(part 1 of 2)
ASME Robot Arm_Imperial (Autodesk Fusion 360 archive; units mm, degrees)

design "ASME Robot Arm - Imperial" references "Hexagon Socket Head Cap Screw ANSI B18.3 - 1/4-28 UNF x 3/8 Steel Grade 2 Plain"
parameter "d400" = 0
sketch "Sketch1" plane through (0, 0, 0) normal (0, 1, 0) x axis (1, 0, 0)
  line L1 (125, 0) -> (0, 0)
  line L2 (0, -40) -> (0, 0)
  line L3 (125, -15) -> (125, 0)
  line L4 (115, -15) -> (125, -15)
  line L5 (60, -45) -> (60, -40)
  curve K1 (115, -15) -> (60, -40)
  line L6 (55, -40) -> (60, -40)
  line L7 (55, -33) -> (55, -40)
  line L8 (54, -33) -> (55, -33)
  line L9 (54, -28) -> (54, -33)
  line L10 (55, -28) -> (54, -28)
  line L11 (55, -15.5519) -> (55, -28)
  line L12 (64, -8) -> (55, -15.5519)
  line L13 (64, 0) -> (64, -8)
  point P1 (0, 0)
  point P2 (0, 0)
  point P4 (0, 0)
  point P5 (0, -40)
  point P8 (60, -40)
  point P17 (64, 0)
  point P3 (125, 0)
  point P6 (125, -15)
  point P7 (115, -15)
  point P9 (60, -45)
  point P10 (55, -40)
  point P11 (55, -33)
  point P12 (54, -33)
  point P13 (54, -28)
  point P16 (64, -8)
  coincident P1 P2
  horizontal L1
  coincident P1 P4
  perpendicular L1 L2
  perpendicular L1 L3
  perpendicular L3 L4
  horizontal P5 P8
  perpendicular L5 L6
  perpendicular L6 L7
  perpendicular L7 L8
  perpendicular L8 L9
  perpendicular L9 L10
  perpendicular L4 L11
  coincident L1 P17
  perpendicular L1 L13
  collinear L7 L11
  dimension "d2" distance P4 P5 = 40
  dimension "d3" = 250
  dimension "d4" distance P3 P6 = 15
  dimension "d5" distance P6 P7 = 10
  dimension "d9" distance P8 P9 = 5
  dimension "d16" = 120
  dimension "d17" distance P8 P10 = 5
  dimension "d18" distance P10 P11 = 7
  dimension "d19" distance P12 P13 = 5
  dimension "d20" distance P16 P17 = 8
  dimension "d21" = 128
  dimension "d22" angle L12 L13 = 50
  dimension "d23" = 108
revolve "Revolve1" sketch "Sketch1" AlongAngle 360
sketch "Sketch2" plane through (0, 0, 40) normal (0, 0, 1) x axis (-1, 0, 0)
  line L1 (0, 100) -> (0, 0)
  circle C1 centre (0, 0) radius 30
  circle C2 centre (0, 0) radius 25
  circle C3 centre (0, 0) radius 60
  circle C4 centre (0, 0) radius 55
  point P2 (0, 0)
  point P3 (0, 100)
  vertical L1
  dimension "d8" distance P2 P3 = 100
hole "Hole1" HoleDiameter 9 TipAngle 118 CBDepth 33 CBDiameter 15
circular_pattern "C-Pattern1" TotalAngle 360
sketch "Sketch1" plane through (0, 0, 0) normal (1, 0, 0) x axis (0, 1, 0)
sketch "Sketch2" plane through (0, 0, 0) normal (1, 0, 0) x axis (0, 1, 0)
  line L1 (0, 225) -> (0, 0)
  line L2 (-55, 40) -> (55, 40)
  line L3 (-55, 181.6987) -> (-55, 40)
  curve K1 (-55, 145) -> (-70, 225)
  curve K2 (-53.2004, 137.205) -> (-56.7996, 152.795)
  curve K3 (-70, 217) -> (-70, 233)
  curve K4 (55, 145) -> (70, 225)
  curve K5 (70, 217) -> (70, 233)
  curve K6 (53.2004, 137.205) -> (56.7996, 152.795)
  line L4 (55, 145) -> (-55, 145)
  circle C1 centre (0, 225) radius 70
  point P1 (0, 0)
  point P2 (0, 0)
  point P3 (0, 225)
  point P6 (0, 225)
  point P5 (-55, 40)
  point P7 (-55, 40)
  point P8 (-55, 181.6987)
  point P9 (-70, 225)
  point P10 (-55, 145)
  point P15 (70, 225)
  point P16 (55, 145)
  point P11 (-56.7996, 152.795)
  point P19 (56.7996, 152.795)
  point P12 (-53.2004, 137.205)
  point P20 (53.2004, 137.205)
  point P13 (-70, 233)
  point P17 (70, 233)
  point P14 (-70, 217)
  point P18 (70, 217)
  coincident P1 P2
  vertical L1
  coincident P3 P6
  coincident P5 P7
  coincident C1 P8
  perpendicular L2 L3
  coincident C1 P9
  coincident L3 P10
  midpoint P10 K2
  midpoint P9 K3
  vertical K3
  horizontal P6 P9
  symmetric L1 P9 P15
  symmetric L1 P10 P16
  symmetric L1 P11 P19
  symmetric L1 P12 P20
  symmetric L1 P13 P17
  symmetric L1 P14 P18
  dimension "d24" distance P3 L2 = 185
  dimension "d25" diameter C1 = 140
  dimension "d26" distance P11 P12 = 16
  dimension "d27" distance P13 P14 = 16
  dimension "d28" distance P6 P10 = 80
  dimension "d31" angle L3 K2 = 13
extrude "Extrude1" new body sketch "Sketch2" profile of C1 K1 K4 L4 distance 130
work_plane "WorkPlane1" AlongDistance 5
sketch "Sketch3" plane through (0, 0, 45) normal (0, 0, 1) x axis (-1, 0, 0)
  circle C1 centre (0, 0) radius 60
  circle C2 centre (0, 0) radius 55
  circle C3 centre (0, 0) radius 60
loft "Loft1" sketch "Sketch3" Start TakeOff Angle 0
sketch "Sketch4" plane through (0, 0, 0) normal (0, 1, 0) x axis (1, 0, 0)
  line L1 (65, -295) -> (-65, -295)
  line L2 (30, -295) -> (-30, -295)
  line L3 (30, -153) -> (30, -295)
  line L4 (-30, -153) -> (30, -153)
  line L5 (-30, -295) -> (-30, -153)
  line L6 (0, -153) -> (0, -295)
  point P4 (-30, -295)
  point P8 (0, -295)
  point P9 (0, -153)
  point P6 (30, -153)
  point P7 (-30, -153)
  point P10 (65, -225)
  horizontal L2
  vertical L3
  horizontal L4
  vertical L5
  coincident L1 P4
  midpoint L1 P8
  midpoint L4 P9
  midpoint L1 L2
  dimension "d36" distance P6 P7 = 60
  dimension "d37" distance L4 P10 = 72
extrude "Extrude2" cut sketch "Sketch4" profile of L1 L2 L3 L4 L5 no distance stored
as_built_joint "As-built1" OffsetX 0 OffsetY 0 OffsetZ 0 AngleZ 0
sketch "Sketch1" plane through (0, 0, 0) normal (1, 0, 0) x axis (0, 1, 0)
  line L1 (0, 575) -> (0, 225)
  curve K1 (46.9846, 557.899) -> (63.4415, 254.5833)
  curve K2 (63.4408, 254.5848) -> (63.4423, 254.5817)
  curve K3 (48.4834, 566.399) -> (45.4858, 549.399)
  line L2 (46.9846, 557.899) -> (0, 575)
  line L3 (50, 575) -> (0, 575)
  line L4 (63.4415, 254.5833) -> (0, 225)
  curve K4 (-46.9846, 557.899) -> (-63.4415, 254.5833)
  curve K5 (-63.4408, 254.5848) -> (-63.4423, 254.5817)
  curve K6 (-48.4834, 566.399) -> (-45.4858, 549.399)
  line L5 (46.9846, 557.899) -> (-46.9846, 557.899)
  line L6 (63.4415, 254.5833) -> (-63.4415, 254.5833)
  arc A1 centre (0, 225) radius 70 clockwise from (-70, 225) to (70, 225)
  circle C1 centre (0, 225) radius 70
  circle C2 centre (0, 575) radius 50
  point P2 (70, 225)
  point P5 (0, 225)
  point P6 (0, 225)
  point P8 (63.4415, 254.5833)
  point P9 (46.9846, 557.899)
  point P14 (0, 575)
  point P15 (46.9846, 557.899)
  point P16 (0, 575)
  point P17 (0, 575)
  point P18 (50, 575)
  point P4 (0, 225)
  point P19 (0, 225)
  point P7 (0, 575)
  point P10 (63.4423, 254.5817)
  point P20 (-63.4415, 254.5833)
  point P21 (-46.9846, 557.899)
  point P22 (-63.4423, 254.5817)
  point P11 (63.4408, 254.5848)
  point P23 (-63.4408, 254.5848)
  point P12 (45.4858, 549.399)
  point P24 (-45.4858, 549.399)
  point P13 (48.4834, 566.399)
  point P25 (-48.4834, 566.399)
  concentric A1 C1
  coincident P2 C1
  coincident P5 P6
  vertical L1
  coincident A1 P8
  midpoint P8 K2
  midpoint P9 K3
  vertical P5 P14
  coincident C2 P15
  coincident P14 P16
  coincident P14 P17
  coincident C2 P18
  horizontal L3
  tangent C1 K2
  coincident P4 P19
  coincident P7 P14
  coincident P9 C2
  coincident K3 P15
  coincident A1 P10
  coincident C1 P10
  symmetric L1 P8 P20
  symmetric L1 P9 P21
  symmetric L1 P10 P22
  symmetric L1 P11 P23
  symmetric L1 P12 P24
  symmetric L1 P13 P25
  dimension "d50" diameter C2 = 100
  dimension "d51" distance P5 P14 = 350
  dimension "d52" angle L2 L3 = 20
  dimension "d54" angle L1 L4 = 65
  dimension "d55" angle K3 L3 = 80
  dimension "d56" distance P12 P13 = 17
extrude "Extrude1" new body sketch "Sketch1" profile of C1 distance 29
extrude "Extrude2" new body sketch "Sketch1" profile of C2 distance 45
split_face "SplitFace1"
split_face "SplitFace2"
sketch "Sketch2" plane through (0, 0, 0) normal (0, 1, 0) x axis (1, 0, 0)
  line L1 (29, -295) -> (-29, -295)
  line L2 (-22.5, -525) -> (22.5, -525)
  curve K1 (22.5, -525) -> (29, -295)
  line L3 (0, -557.2354) -> (0, -225)
  curve K2 (22.5, -547.5) -> (22.5, -502.5)
  curve K3 (29, -317.5) -> (29, -272.5)
  curve K4 (-22.5, -525) -> (-29, -295)
  curve K5 (-29, -317.5) -> (-29, -272.5)
  curve K6 (-22.5, -547.5) -> (-22.5, -502.5)
  point P3 (29, -295)
  point P6 (29, -295)
  point P4 (22.5, -525)
  point P7 (22.5, -525)
  point P8 (0, -225)
  point P9 (0, -225)
  point P15 (-29, -295)
  point P16 (-22.5, -525)
  point P11 (22.5, -502.5)
  point P19 (-22.5, -502.5)
  point P12 (22.5, -547.5)
  point P20 (-22.5, -547.5)
  point P13 (29, -272.5)
  point P17 (-29, -272.5)
  point P14 (29, -317.5)
  point P18 (-29, -317.5)
  coincident P3 P6
  coincident P4 P7
  coincident P8 P9
  perpendicular L2 L3
  midpoint P7 K2
  vertical K2
  midpoint P6 K3
  vertical K3
  symmetric P6 L3 P15
  symmetric P7 L3 P16
  symmetric L3 P11 P19
  symmetric L3 P12 P20
  symmetric L3 P13 P17
  symmetric L3 P14 P18
  dimension "d59" distance P11 P12 = 45
  dimension "d60" distance P13 P14 = 45
loft "Loft1"
as_built_joint "As-built2" OffsetX 0 OffsetY 0 OffsetZ 0 AngleZ 0 RotateMinimum -107 RotateMaximum 107
sketch "Sketch1" plane through (0, 0, 0) normal (1, 0, 0) x axis (0, 1, 0)
  line L1 (0, 925) -> (0, 575)
  line L2 (45.3154, 596.1309) -> (0, 575)
  line L3 (36.2222, 915.2943) -> (0, 925)
  curve K1 (36.2222, 915.2943) -> (45.3154, 596.1309)
  curve K2 (42.2511, 937.7943) -> (30.1934, 892.7943)
  curve K3 (34.8235, 618.6309) -> (55.8073, 573.6309)
  curve K4 (-36.2222, 915.2943) -> (-45.3154, 596.1309)
  curve K5 (-34.8235, 618.6309) -> (-55.8073, 573.6309)
  curve K6 (-42.2511, 937.7943) -> (-30.1934, 892.7943)
  line L4 (-45.3154, 596.1309) -> (45.3154, 596.1309)
  line L5 (-36.2222, 915.2943) -> (36.2222, 915.2943)
  arc A1 centre (0, 575) radius 50 clockwise from (-46.9846, 557.899) to (46.9846, 557.899)
  circle C1 centre (0, 575) radius 50
  circle C2 centre (0, 925) radius 37.5
  point P2 (46.9846, 557.899)
  point P4 (0, 575)
  point P7 (0, 575)
  point P6 (0, 925)
  point P8 (0, 925)
  point P9 (0, 575)
  point P10 (45.3154, 596.1309)
  point P11 (0, 925)
  point P12 (36.2222, 915.2943)
  point P17 (-45.3154, 596.1309)
  point P18 (-36.2222, 915.2943)
  point P13 (30.1934, 892.7943)
  point P21 (-30.1934, 892.7943)
  point P14 (42.2511, 937.7943)
  point P22 (-42.2511, 937.7943)
  point P15 (55.8073, 573.6309)
  point P19 (-55.8073, 573.6309)
  point P16 (34.8235, 618.6309)
  point P20 (-34.8235, 618.6309)
  point P5 (0, 575)
  concentric A1 C1
  coincident P2 C1
  coincident P4 P7
  coincident P6 P8
  vertical L1
  coincident P4 P9
  coincident C1 P10
  coincident P6 P11
  coincident C2 P12
  midpoint P12 K2
  midpoint P10 K3
  symmetric L1 P10 P17
  symmetric L1 P12 P18
  symmetric L1 P13 P21
  symmetric L1 P14 P22
  symmetric L1 P15 P19
  symmetric L1 P16 P20
  tangent C1 K3
  tangent C2 K2
  dimension "d65" diameter C2 = 75
  dimension "d66" distance P5 P6 = 350
  dimension "d67" angle L1 L2 = 65
  dimension "d68" angle L1 L3 = 75
  dimension "d71" distance P13 P14 = 45
  dimension "d72" distance P15 P16 = 45
extrude "Extrude1" new body sketch "Sketch1" profile of C1 L4 distance 100
extrude "Extrude2" new body sketch "Sketch1" profile of C2 L5 distance 80
sketch "Sketch2" plane through (0, 0, 0) normal (0, 1, 0) x axis (1, 0, 0)
  line L1 (-50, -625) -> (-50, -525)
  line L2 (-40, -962.5) -> (-40, -887.5)
  curve K1 (-40, -887.5) -> (-50, -625)
  curve K2 (-40, -915) -> (-40, -860)
  curve K3 (-50, -652.5) -> (-50, -597.5)
  line L3 (0, -911.4032) -> (0, -575)
  curve K4 (40, -887.5) -> (50, -625)
  curve K5 (50, -652.5) -> (50, -597.5)
  curve K6 (40, -915) -> (40, -860)
  line L4 (0, -915.2943) -> (0, -596.1309)
  point P3 (-50, -625)
  point P6 (-50, -625)
  point P4 (-40, -887.5)
  point P7 (-40, -887.5)
  point P12 (0, -575)
  point P13 (0, -575)
  point P15 (50, -625)
  point P16 (40, -887.5)
  point P8 (-40, -860)
  point P19 (40, -860)
  point P9 (-40, -915)
  point P20 (40, -915)
  point P10 (-50, -597.5)
  point P17 (50, -597.5)
  point P11 (-50, -652.5)
  point P18 (50, -652.5)
  coincident P3 P6
  coincident P4 P7
  midpoint P7 K2
  midpoint P6 K3
  coincident P12 P13
  vertical L3
  symmetric P6 L3 P15
  symmetric P7 L3 P16
  symmetric P8 L3 P19
  symmetric P9 L3 P20
  symmetric P10 L3 P17
  symmetric P11 L3 P18
  vertical K3
  vertical K2
  dimension "d77" distance P8 P9 = 55
  dimension "d78" distance P10 P11 = 55
split_face "SplitFace1"
split_face "SplitFace2"
work_plane "WorkPlane1" RotateAngle 0
work_plane "WorkPlane2" AlongDistance 40
sketch "Sketch4" plane through (0, 0, 847.5) normal (0, 0, -1) x axis (-1, 0, 0)
  circle C1 centre (0, 0) radius 42.5
  point P1 (0, 0)
  point P2 (0, 0)
  coincident P1 P2
  dimension "d92" diameter C1 = 85
loft "Loft2" sketch "Sketch4"
sketch "Sketch1" plane through (0, 0, 0) normal (1, 0, 0) x axis (0, 1, 0)
  line L1 (0, 925) -> (0, 575)
  line L2 (45.3154, 596.1309) -> (0, 575)
  line L3 (36.2222, 915.2943) -> (0, 925)
  curve K1 (36.2222, 915.2943) -> (45.3154, 596.1309)
  curve K2 (42.2511, 937.7943) -> (30.1934, 892.7943)
  curve K3 (37.1261, 618.6309) -> (53.5047, 573.6309)
  curve K4 (-36.2222, 915.2943) -> (-45.3154, 596.1309)
  curve K5 (-37.1261, 618.6309) -> (-53.5047, 573.6309)
  curve K6 (-42.2511, 937.7943) -> (-30.1934, 892.7943)
  line L4 (-45.3154, 596.1309) -> (45.3154, 596.1309)
  line L5 (-36.2222, 915.2943) -> (36.2222, 915.2943)
  arc A1 centre (0, 575) radius 50 clockwise from (-46.9846, 557.899) to (46.9846, 557.899)
  circle C1 centre (0, 575) radius 50
  circle C2 centre (0, 925) radius 37.5
  point P2 (46.9846, 557.899)
  point P4 (0, 575)
  point P7 (0, 575)
  point P6 (0, 925)
  point P8 (0, 925)
  point P9 (0, 575)
  point P10 (45.3154, 596.1309)
  point P11 (0, 925)
  point P12 (36.2222, 915.2943)
  point P17 (-45.3154, 596.1309)
  point P18 (-36.2222, 915.2943)
  point P13 (30.1934, 892.7943)
  point P21 (-30.1934, 892.7943)
  point P14 (42.2511, 937.7943)
  point P22 (-42.2511, 937.7943)
  point P15 (53.5047, 573.6309)
  point P19 (-53.5047, 573.6309)
  point P16 (37.1261, 618.6309)
  point P20 (-37.1261, 618.6309)
  point P5 (0, 575)
  concentric A1 C1
  coincident P2 C1
  coincident P4 P7
  coincident P6 P8
  vertical L1
  coincident P4 P9
  coincident C1 P10
  coincident P6 P11
  coincident C2 P12
  midpoint P12 K2
  midpoint P10 K3
  symmetric L1 P10 P17
  symmetric L1 P12 P18
  symmetric L1 P13 P21
  symmetric L1 P14 P22
  symmetric L1 P15 P19
  symmetric L1 P16 P20
  dimension "d65_1" diameter C2 = 75
  dimension "d66_1" distance P5 P6 = 350
  dimension "d67_1" angle L1 L2 = 65
  dimension "d68_1" angle L1 L3 = 75
  dimension "d69_1" angle L2 K3 = 85
  dimension "d70_1" angle L1 K2 = 15
  dimension "d71_1" distance P13 P14 = 45
  dimension "d72_1" distance P15 P16 = 45
extrude "Extrude1" new body sketch "Sketch1" profile of C1 L4 distance 100 named "d73_1"
extrude "Extrude2" new body sketch "Sketch1" profile of C2 L5 distance 80 named "d75_1"
sketch "Sketch2" plane through (0, 0, 0) normal (0, 1, 0) x axis (1, 0, 0)
  line L1 (-50, -625) -> (-50, -525)
  line L2 (-40, -962.5) -> (-40, -887.5)
  curve K1 (-40, -887.5) -> (-50, -625)
  curve K2 (-47.1175, -914.063) -> (-32.8825, -860.937)
  curve K3 (-42.8825, -651.563) -> (-57.1175, -598.437)
  line L3 (0, -911.4032) -> (0, -575)
  curve K4 (40, -887.5) -> (50, -625)
  curve K5 (42.8825, -651.563) -> (57.1175, -598.437)
  curve K6 (47.1175, -914.063) -> (32.8825, -860.937)
  line L4 (0, -915.2943) -> (0, -596.1309)
  point P3 (-50, -625)
  point P6 (-50, -625)
  point P4 (-40, -887.5)
  point P7 (-40, -887.5)
  point P12 (0, -575)
  point P13 (0, -575)
  point P15 (50, -625)
  point P16 (40, -887.5)
  point P8 (-32.8825, -860.937)
  point P19 (32.8825, -860.937)
  point P9 (-47.1175, -914.063)
  point P20 (47.1175, -914.063)
  point P10 (-57.1175, -598.437)
  point P17 (57.1175, -598.437)
  point P11 (-42.8825, -651.563)
  point P18 (42.8825, -651.563)
  coincident P3 P6
  coincident P4 P7
  midpoint P7 K2
  midpoint P6 K3
  coincident P12 P13
  vertical L3
  symmetric P6 L3 P15
  symmetric P7 L3 P16
  symmetric P8 L3 P19
  symmetric P9 L3 P20
  symmetric P10 L3 P17
  symmetric P11 L3 P18
  dimension "d77_1" distance P8 P9 = 55
  dimension "d78_1" distance P10 P11 = 55
  dimension "d79_1" angle K3 L4 = 15
  dimension "d80_1" angle K2 L4 = 15
split_face "SplitFace1"
split_face "SplitFace2"
work_plane "WorkPlane1" RotateAngle 0 named "d91_1"
work_plane "WorkPlane2" AlongDistance 40 named "d93_1"
sketch "Sketch4" plane through (0, 0, 847.5) normal (0, 0, -1) x axis (-1, 0, 0)
  circle C1 centre (0, 0) radius 42.5
  point P1 (0, 0)
  point P2 (0, 0)
  coincident P1 P2
  dimension "d92_1" diameter C1 = 85
extrude "Extrude4" new body sketch "Sketch4" against normal blind 5
loft "Loft2"
loft "Loft1"
sketch "Sketch3" plane through (0, 0, 0) normal (0, 1, 0) x axis (1, 0, 0)
  line L1 (-50, -525) -> (50, -525)
  line L2 (40, -962.5) -> (-40, -962.5)
  line L3 (-23, -525) -> (23, -525)
  line L4 (-23, -630) -> (-23, -525)
  line L5 (23, -630) -> (-23, -630)
  line L6 (23, -525) -> (23, -630)
  line L7 (-19, -962.5) -> (19, -962.5)
  line L8 (-19, -886.5) -> (-19, -962.5)
  line L9 (19, -886.5) -> (-19, -886.5)
  line L10 (19, -962.5) -> (19, -886.5)
  point P6 (23, -525)
  point P10 (19, -962.5)
  point P8 (-23, -630)
  point P9 (23, -630)
  point P7 (-23, -525)
  point P11 (-19, -962.5)
  point P12 (-19, -886.5)
  horizontal L3
  vertical L4
  horizontal L5
  vertical L6
  coincident L1 P6
  midpoint L1 L3
  horizontal L7
  vertical L8
  horizontal L9
  vertical L10
  coincident L2 P10
  midpoint L2 L7
  dimension "d81" distance P8 P9 = 46
  dimension "d82" distance P7 P8 = 105
  dimension "d83" distance P10 P11 = 38
  dimension "d84" distance P11 P12 = 76
extrude "Extrude3" cut sketch "Sketch3" distance 150
remove_body "RemoveBody1"
as_built_joint "As-built3" OffsetX 0 OffsetY 0 OffsetZ 0 AngleZ 0 RotateMinimum -105 RotateMaximum 105
sketch "Sketch3" plane through (0, 0, 0) normal (0, 1, 0) x axis (1, 0, 0)
  line L1 (-50, -525) -> (50, -525)
  line L2 (40, -962.5) -> (-40, -962.5)
  line L3 (-23, -525) -> (23, -525)
  line L4 (-23, -630) -> (-23, -525)
  line L5 (23, -630) -> (-23, -630)
  line L6 (23, -525) -> (23, -630)
  line L7 (-19, -962.5) -> (19, -962.5)
  line L8 (-19, -886.5) -> (-19, -962.5)
  line L9 (19, -886.5) -> (-19, -886.5)
  line L10 (19, -962.5) -> (19, -886.5)
  point P6 (23, -525)
  point P10 (19, -962.5)
  point P8 (-23, -630)
  point P9 (23, -630)
  point P7 (-23, -525)
  point P11 (-19, -962.5)
  point P12 (-19, -886.5)
  horizontal L3
  vertical L4
  horizontal L5
  vertical L6
  coincident L1 P6
  midpoint L1 L3
  horizontal L7
  vertical L8
  horizontal L9
  vertical L10
  coincident L2 P10
  midpoint L2 L7
  dimension "d81_1" distance P8 P9 = 46
  dimension "d82_1" distance P7 P8 = 105
  dimension "d83_1" distance P10 P11 = 38
  dimension "d84_1" distance P11 P12 = 76
extrude "Extrude5" cut sketch "Sketch3" profile of L2 L7 L8 L9 L10 no distance stored
remove_body "RemoveBody1"
as_built_joint "As-built4" OffsetX 0 OffsetY 0 OffsetZ 0 AngleZ 0
sketch "Sketch1" plane through (0, 0, 0) normal (1, 0, 0) x axis (0, 1, 0)
  line L1 (-35.2385, 937.8258) -> (35.2385, 937.8258)
  line L2 (-35.2385, 937.8258) -> (0, 925)
  line L3 (0, 962.5) -> (0, 925)
  arc A1 centre (0, 925) radius 37.5 clockwise from (-36.2222, 915.2943) to (36.2222, 915.2943)
  circle C1 centre (0, 925) radius 37.5
  point P3 (-36.2222, 915.2943)
  point P6 (35.2385, 937.8258)
  point P7 (-35.2385, 937.8258)
  point P5 (0, 925)
  point P8 (0, 925)
  point P9 (-35.2385, 937.8258)
  point P10 (0, 925)
  point P11 (0, 962.5)
  concentric A1 C1
  coincident P3 C1
  coincident A1 P6
  coincident C1 P7
  horizontal L1
  coincident P5 P8
  coincident P7 P9
  coincident P5 P10
  midpoint A1 P11
  dimension "d109" angle L2 L3 = 70
extrude "Extrude1" new body sketch "Sketch1" profile of A1 C1 L1 distance 37.5
work_plane "WorkPlane1" RotateAngle 0
work_plane "WorkPlane2" AlongDistance 50
sketch "Sketch2" plane through (0, 0, 1012.5) normal (0, 0, 1) x axis (1, 0, 0)
  circle C1 centre (0, 0) radius 50
  point P1 (0, 0)
  point P2 (0, 0)
  coincident P1 P2
  dimension "d106" diameter C1 = 100
extrude "Extrude2" new body sketch "Sketch2" along normal blind 10
split_face "SplitFace1"
sketch "Sketch3" plane through (0, 0, 0) normal (0, 1, 0) x axis (1, 0, 0)
  line L1 (-18.75, -962.5) -> (-18.75, -937.8258)
  line L2 (0, -1012.5) -> (0, 0)
  line L3 (50, -1012.5) -> (-50, -1012.5)
  curve K1 (-50, -1012.5) -> (-18.75, -962.5)
  curve K2 (-51.6246, -1017.5) -> (-48.3754, -1007.5)
  curve K3 (-21.9992, -972.5) -> (-15.5008, -952.5)
  curve K4 (50, -1012.5) -> (18.75, -962.5)
  curve K5 (21.9992, -972.5) -> (15.5008, -952.5)
  curve K6 (51.6246, -1017.5) -> (48.3754, -1007.5)
  point P1 (0, 0)
  point P4 (0, 0)
  point P5 (0, -1012.5)
  point P3 (-18.75, -962.5)
  point P8 (-18.75, -962.5)
  point P6 (-50, -1012.5)
  point P9 (-50, -1012.5)
  point P14 (18.75, -962.5)
  point P15 (50, -1012.5)
  point P10 (-48.3754, -1007.5)
  point P18 (48.3754, -1007.5)
  point P11 (-51.6246, -1017.5)
  point P19 (51.6246, -1017.5)
  point P12 (-15.5008, -952.5)
  point P16 (15.5008, -952.5)
  point P13 (-21.9992, -972.5)
  point P17 (21.9992, -972.5)
  coincident P1 P4
  parallel L1 L2
  midpoint P5 L3
  coincident P3 P8
  coincident P6 P9
  midpoint P9 K2
  midpoint P8 K3
  parallel K2 K3
  symmetric L2 P8 P14
  symmetric L2 P9 P15
  symmetric L2 P10 P18
  symmetric L2 P11 P19
  symmetric L2 P12 P16
  symmetric L2 P13 P17
  dimension "d110" angle L2 K3 = 18
  dimension "d111" distance P12 P13 = 20
  dimension "d112" distance P10 P11 = 10
sketch "Sketch4" plane through (0, 0, 0) normal (1, 0, 0) x axis (0, 1, 0)
  line L1 (-50, 1012.5) -> (50, 1012.5)
  curve K1 (50, 1012.5) -> (35.2385, 937.8258)
  curve K2 (35.2385, 945.3258) -> (35.2385, 930.3258)
  curve K3 (53.4973, 1020) -> (46.5027, 1005)
  line L2 (0, 1012.5) -> (0, 962.5)
  line L3 (0, 1012.5) -> (0, 0)
  curve K4 (-50, 1012.5) -> (-35.2385, 937.8258)
  curve K5 (-35.2385, 945.3258) -> (-35.2385, 930.3258)
  curve K6 (-53.4973, 1020) -> (-46.5027, 1005)
  arc A1 centre (0, 925) radius 37.5 clockwise from (-36.2222, 915.2943) to (36.2222, 915.2943)
  point P5 (50, 1012.5)
  point P8 (50, 1012.5)
  point P7 (35.2385, 937.8258)
  point P17 (-35.2385, 937.8258)
  point P18 (-50, 1012.5)
  point P9 (35.2385, 930.3258)
  point P19 (-35.2385, 930.3258)
  point P10 (35.2385, 945.3258)
  point P20 (-35.2385, 945.3258)
  point P11 (46.5027, 1005)
  point P21 (-46.5027, 1005)
  point P12 (53.4973, 1020)
  point P22 (-53.4973, 1020)
  point P23 (35.2385, 937.8258)
  coincident P5 P8
  midpoint P7 K2
  vertical K2
  midpoint P8 K3
  symmetric P7 L3 P17
  symmetric P8 L3 P18
  symmetric P9 L3 P19
  symmetric P10 L3 P20
  symmetric P11 L3 P21
  symmetric P12 L3 P22
  coincident P7 P23
  dimension "d113" angle K3 L2 = 25
  dimension "d115" distance P11 P12 = 15
  dimension "d116" distance P9 P10 = 15
loft "Loft1"
as_built_joint "As-built5" OffsetX 0 OffsetY 0 OffsetZ 0 AngleZ 0 RotateMinimum -92 RotateMaximum 92
sketch "Sketch1" plane through (0, 0, 0) normal (0, 1, 0) x axis (1, 0, 0)
  line L1 (50, -1022.5) -> (-50, -1022.5)
  line L2 (0, -1035.708) -> (0, -1020.468)
  line L3 (-50, -1032.66) -> (-50, -1022.5)
  line L4 (-34.163, -1032.66) -> (-50, -1032.66)
  line L5 (-34.163, -1031.644) -> (-34.163, -1032.66)
  line L6 (-31.115, -1031.644) -> (-34.163, -1031.644)
  line L7 (-31.115, -1032.66) -> (-31.115, -1031.644)
  line L8 (-27.305, -1032.66) -> (-31.115, -1032.66)
  line L9 (-27.305, -1035.708) -> (-27.305, -1032.66)
  line L10 (0, -1035.708) -> (-27.305, -1035.708)
  line L11 (-27.305, -1022.5) -> (-50, -1022.5)
  line L12 (-27.305, -1020.468) -> (-27.305, -1022.5)
  line L13 (0, -1020.468) -> (-27.305, -1020.468)
  point P8 (-34.163, -1032.66)
  point P2 (-50, -1022.5)
  point P6 (-50, -1022.5)
  point P14 (-50, -1022.5)
  point P15 (-27.305, -1022.5)
  point P4 (0, -1020.468)
  point P17 (0, -1020.468)
  point P18 (0, -1022.5)
  point P12 (-27.305, -1032.66)
  point P5 (0, -1035.708)
  point P9 (-34.163, -1031.644)
  point P10 (-31.115, -1031.644)
  point P16 (-27.305, -1020.468)
  perpendicular L1 L2
  perpendicular L1 L3
  perpendicular L3 L4
  perpendicular L4 L5
  perpendicular L5 L6
  perpendicular L6 L7
  perpendicular L5 L8
  perpendicular L8 L9
  perpendicular L2 L10
  coincident P8 L8
  coincident P2 L3
  coincident P2 P6
  coincident P2 P14
  coincident L1 P15
  perpendicular L3 L11
  perpendicular L1 L12
  perpendicular L12 L13
  coincident P4 P17
  midpoint L1 P18
  coincident L2 P18
  coincident P12 L12
  dimension "d121" distance P4 P5 = 15.24
  dimension "d123" distance P9 P10 = 3.048
  dimension "d124" distance P8 P9 = 1.016
  dimension "d125" = 62.23
  dimension "d126" = 54.61
  dimension "d167" distance L1 L4 = 10.16
  dimension "d169" distance P15 P16 = 2.032
revolve "Revolve1" sketch "Sketch1" AlongAngle 360
sketch "Sketch2" plane through (0, 0, 1032.66) normal (0, 0, 1) x axis (-1, 0, 0)
  line L1 (0, 41.91) -> (0, 0)
  circle C1 centre (0, 0) radius 34.163
  circle C2 centre (0, 0) radius 50
  point P2 (0, 0)
  point P3 (0, 0)
  point P4 (0, 41.91)
  coincident P2 P3
  vertical L1
  dimension "d128" distance P3 P4 = 41.91
hole "Hole1" HoleDepth 20 HoleDiameter 6.7564 TipAngle 180 CBDepth 6.35 CBDiameter 11.1252
circular_pattern "C-Pattern1" TotalAngle 360
sketch "Sketch3" plane through (0, 0, 1035.708) normal (0, 0, 1) x axis (-1, 0, 0)
  line L1 (0, 20) -> (0, 0)
  line L2 (8.4853, 8.4853) -> (0, 0)
  line L3 (10, 0) -> (0, 0)
  circle C1 centre (0, 0) radius 27.305
  point P2 (0, 0)
  point P3 (0, 0)
  point P5 (0, 0)
  point P4 (0, 20)
  point P6 (8.4853, 8.4853)
  coincident P2 P3
  vertical L1
  horizontal L3
  coincident P2 P5
  dimension "d136" distance P3 P4 = 20
  dimension "d137" distance P5 P6 = 12
  dimension "d138" angle L2 L3 = 45
hole "Hole1" HoleDepth 20 HoleDiameter 4.234 TipAngle 180
circular_pattern "C-Pattern2" TotalAngle 360
hole "Hole2" HoleDepth 20 HoleDiameter 4.234 TipAngle 180
as_built_joint "As-built6" OffsetX 0 OffsetY 0 OffsetZ 0 AngleZ 0
extrude "Extrude3" add of existing geometry to an object
sketch "Sketch5" plane through (0, 0, 0) normal (0, 1, 0) x axis (1, 0, 0)
  line L1 (0, -1022.5) -> (0, -1017.5)
  line L2 (-50, -1022.5) -> (50, -1022.5)
  line L3 (27.55, -1017.5) -> (0, -1017.5)
  line L4 (27.55, -1022.5) -> (27.55, -1017.5)
  line L5 (0, -1022.5) -> (27.55, -1022.5)
  point P3 (0, -1022.5)
  point P7 (27.55, -1022.5)
  point P2 (0, -1017.5)
  vertical L1
  midpoint P3 L2
  perpendicular L1 L3
  coincident L2 P7
  perpendicular L2 L4
  dimension "d170" distance P2 P3 = 5
  dimension "d171" = 55.1
revolve "Revolve1" sketch "Sketch5" AlongAngle 360
sketch "Sketch6" plane through (0, 0, 1022.5) normal (0, 0, 1) x axis (-1, 0, 0)
  circle C1 centre (0, 0) radius 27.55
  circle C2 centre (0, 0) radius 50
  circle C3 centre (0, 41.91) radius 3.3782
hole "Hole3" HoleDepth 15 HoleDiameter 4.234 TipAngle 180
circular_pattern "C-Pattern1" TotalAngle 360
chamfer "Chamfer1" distance 3 distance 1 distance 0.5
fillet "Fillet1" radius 3
fillet "Fillet2" radius 35
fillet "Fillet1" radius 8 15
fillet "Fillet1" radius 200 10
sketch "Sketch3" plane through (0, 0, 0) normal (1, 0, 0) x axis (0, 1, 0)
  line L1 (0, 490) -> (0, 340)
  curve K1 (24.1481, 483.5295) -> (33.8074, 349.0587)
  line L2 (33.8074, 349.0587) -> (0, 340)
  curve K2 (24.8557, 497.0295) -> (23.4406, 470.0295)
  line L3 (24.1481, 483.5295) -> (0, 490)
  curve K3 (-24.1481, 483.5295) -> (-33.8074, 349.0587)
  curve K4 (32.2112, 362.0587) -> (35.4036, 336.0587)
  curve K5 (-32.2112, 362.0587) -> (-35.4036, 336.0587)
  curve K6 (-24.8557, 497.0295) -> (-23.4406, 470.0295)
  circle C1 centre (0, 490) radius 25
  circle C2 centre (0, 340) radius 35
  arc A1 centre (0, 225) radius 70 clockwise from (-70, 225) to (70, 225)
  point P3 (0, 340)
  point P4 (0, 340)
  point P2 (0, 490)
  point P5 (0, 490)
  point P1 (0, 0)
  point P9 (33.8074, 349.0587)
  point P10 (24.1481, 483.5295)
  point P11 (0, 340)
  point P14 (0, 490)
  point P15 (-33.8074, 349.0587)
  point P16 (-24.1481, 483.5295)
  point P12 (23.4406, 470.0295)
  point P21 (-23.4406, 470.0295)
  point P13 (24.8557, 497.0295)
  point P22 (-24.8557, 497.0295)
  point P17 (35.4036, 336.0587)
  point P19 (-35.4036, 336.0587)
  point P18 (32.2112, 362.0587)
  point P20 (-32.2112, 362.0587)
  point P8 (0, 225)
  coincident P3 P4
  coincident P2 P5
  vertical L1
  coincident P1 L1
  coincident C2 P9
  coincident C1 P10
  coincident P3 P11
  midpoint P10 K2
  coincident P2 P14
  midpoint P9 K4
  symmetric L1 P9 P15
  symmetric L1 P10 P16
  symmetric L1 P12 P21
  symmetric L1 P13 P22
  symmetric L1 P17 P19
  symmetric L1 P18 P20
  dimension "d196" diameter C2 = 70
  dimension "d197" diameter C1 = 50
  dimension "d198" distance P3 P8 = 115
  dimension "d199" distance P4 P5 = 150
  dimension "d200" angle L1 L2 = 75
  dimension "d201" angle L1 L3 = 75
  dimension "d202" angle L1 K2 = 3
  dimension "d203" angle L1 K4 = 7
  dimension "d204" distance P17 P18 = 26
  dimension "d205" distance P12 P13 = 27
extrude "Extrude3" sketch "Sketch3" profile of C1 C2 K1 K3 blind 5
mirror "Mirror1" mirrorStitchTolerance 0.1
fillet "Fillet2" radius 120
chamfer "Chamfer1" distance 2
sketch "Sketch5" plane through (65, 0, 0) normal (1, 0, 0) x axis (0, 1, 0)
  curve K1 (39.6152, 145) -> (40.3844, 148.3743)
  curve K2 (40.3844, 148.3743) -> (55, 225)
  curve K3 (-55, 225) -> (-40.3844, 148.3743)
  curve K4 (-40.3844, 148.3743) -> (-39.6152, 145)
  line L1 (39.6152, 145) -> (-39.6152, 145)
  arc A1 centre (0, 225) radius 55 clockwise from (-55, 225) to (55, 225)
  arc A2 centre (0, 225) radius 55 clockwise from (-55, 225) to (55, 225)
  circle C1 centre (0, 225) radius 55
  point P10 (-55, 225)
  concentric A2 C1
  coincident P10 C1
work_plane "WorkPlane2" sketch "Sketch5" AlongDistance 6
sketch "Sketch6" plane through (71, 0, 0) normal (1, 0, 0) x axis (0, 1, 0)
loft "Loft2" sketch "Sketch5"
mirror "Mirror1" mirrorStitchTolerance 0.1
fillet "Fillet1" radius 10
fillet "Fillet2" radius 100
fillet "Fillet3" radius 10
fillet "Fillet2" radius 10
fillet "Fillet4" radius 10
work_plane "WorkPlane3" AlongDistance 5
sketch "Sketch5" plane through (55, 0, 0) normal (1, 0, 0) x axis (0, 1, 0)
  arc A1 centre (0, 575) radius 50 clockwise from (45.6932, 595.3011) to (-45.6932, 595.3011)
loft "Loft3"
mirror "Mirror1" mirrorStitchTolerance 0.1
fillet "Fillet5" radius 50
fillet "Fillet4" radius 5
sketch "Sketch7" plane through (0, 0, 0) normal (1, 0, 0) x axis (0, 1, 0)
  line L1 (4.1989, 228.3433) -> (-19.0632, 190.9471)
  line L2 (4.1989, 247.7426) -> (4.1989, 228.3433)
  line L3 (-8.9006, 229.9785) -> (2.1114, 248.3458)
  curve K1 (-12.1232, 228.3672) -> (-8.9006, 229.9785)
  line L4 (-19.0632, 228.3486) -> (-12.1232, 228.3672)
  line L5 (-19.0632, 251.6902) -> (-19.0632, 228.3486)
  line L6 (21.2698, 251.6902) -> (-19.0632, 251.6902)
  line L7 (22.7039, 227.9253) -> (22.7039, 250.1979)
  line L8 (-0.4577, 190.6191) -> (22.7039, 227.9253)
  line L9 (-19.0632, 190.6191) -> (-0.4577, 190.6191)
  line L10 (-19.0632, 190.9471) -> (-19.0632, 190.6191)
  line L11 (17.8557, 598.5641) -> (-14.4108, 598.5641)
  line L12 (-14.4108, 549.7072) -> (0.4736, 549.7072)
  line L13 (-14.4108, 549.9697) -> (-14.4108, 549.7072)
  line L14 (19.0029, 579.5522) -> (19.0029, 597.3703)
  line L15 (-14.4108, 579.8909) -> (-8.8588, 579.9057)
  line L16 (-6.2807, 581.1948) -> (2.5289, 595.8887)
  line L17 (4.1989, 595.4061) -> (4.1989, 579.8867)
  line L18 (4.1989, 579.8867) -> (-14.4108, 549.9697)
  line L19 (0.4736, 549.7072) -> (19.0029, 579.5522)
  line L20 (-14.4108, 598.5641) -> (-14.4108, 579.8909)
  curve K2 (-8.8588, 579.9057) -> (-6.2807, 581.1948)
  curve K3 (-7.553, 924.1916) -> (-5.2327, 925.3517)
  line L21 (-12.5498, 940.9841) -> (-12.5498, 924.1782)
  line L22 (-12.5498, 924.1782) -> (-7.553, 924.1916)
  line L23 (-12.5498, 897.2492) -> (-12.5498, 897.0129)
  line L24 (4.1989, 938.1419) -> (4.1989, 924.1744)
  line L25 (17.5225, 923.8734) -> (17.5225, 939.9097)
  line L26 (0.8461, 897.0129) -> (17.5225, 923.8734)
  line L27 (4.1989, 924.1744) -> (-12.5498, 897.2492)
  line L28 (16.49, 940.9841) -> (-12.5498, 940.9841)
  line L29 (-5.2327, 925.3517) -> (2.6959, 938.5762)
  line L30 (-12.5498, 897.0129) -> (0.8461, 897.0129)
  arc A1 centre (3.0665, 247.7426) radius 1.1324 clockwise from (3.0639, 248.875) to (4.1989, 247.7426)
  arc A2 centre (2.9857, 247.8939) radius 0.9843 clockwise from (2.1114, 248.3458) to (3.0639, 248.875)
  arc A3 centre (21.2738, 250.2588) radius 1.4314 clockwise from (21.2698, 251.6902) to (22.7039, 250.1979)
  arc A4 centre (3.2283, 595.5271) radius 0.7874 clockwise from (2.5289, 595.8887) to (3.2909, 596.312)
  arc A5 centre (3.293, 595.4061) radius 0.9059 clockwise from (3.2909, 596.312) to (4.1989, 595.4061)
  arc A6 centre (17.8588, 597.419) radius 1.1451 clockwise from (17.8557, 598.5641) to (19.0029, 597.3703)
  arc A7 centre (16.4928, 939.9535) radius 1.0306 clockwise from (16.49, 940.9841) to (17.5225, 939.9097)
  arc A8 centre (3.3254, 938.2508) radius 0.7087 clockwise from (2.6959, 938.5762) to (3.3817, 938.9572)
  arc A9 centre (3.3836, 938.1419) radius 0.8153 clockwise from (3.3817, 938.9572) to (4.1989, 938.1419)
emboss "Emboss1" sketch "Sketch7" Depth -2 Horizontal Distance 0 Vertical Distance 0 Rotation Angle 0
emboss "Emboss1" sketch "Sketch7" Depth -2 Horizontal Distance 0 Vertical Distance 0 Rotation Angle 0
emboss "Emboss1" sketch "Sketch7" Depth -2 Horizontal Distance 0 Vertical Distance 0 Rotation Angle 0
sketch "Sketch8" plane through (0, 0, 0) normal (1, 0, 0) x axis (0, 1, 0)
  line L1 (4.3387, 213.8621) -> (-18.9234, 251.2583)
  line L2 (4.3387, 194.4628) -> (4.3387, 213.8621)
  line L3 (-8.7608, 212.2269) -> (2.2512, 193.8596)
  curve K1 (-11.9834, 213.8382) -> (-8.7608, 212.2269)
  line L4 (-18.9234, 213.8568) -> (-11.9834, 213.8382)
  line L5 (-18.9234, 190.5152) -> (-18.9234, 213.8568)
  line L6 (21.4097, 190.5152) -> (-18.9234, 190.5152)
  line L7 (22.8437, 214.2801) -> (22.8437, 192.0075)
  line L8 (-0.3179, 251.5863) -> (22.8437, 214.2801)
  line L9 (-18.9234, 251.5863) -> (-0.3179, 251.5863)
  line L10 (-18.9234, 251.2583) -> (-18.9234, 251.5863)
  line L11 (-14.271, 568.4323) -> (-8.719, 568.4175)
  line L12 (19.1427, 568.771) -> (19.1427, 550.9529)
  line L13 (-14.271, 598.616) -> (0.6134, 598.616)
  line L14 (4.3387, 568.4365) -> (-14.271, 598.3535)
  line L15 (-6.1409, 567.1284) -> (2.6687, 552.4345)
  line L16 (-14.271, 598.3535) -> (-14.271, 598.616)
  line L17 (0.6134, 598.616) -> (19.1427, 568.771)
  curve K2 (-8.719, 568.4175) -> (-6.1409, 567.1284)
  line L18 (17.9955, 549.7591) -> (-14.271, 549.7591)
  line L19 (-14.271, 549.7591) -> (-14.271, 568.4323)
  line L20 (4.3387, 552.9171) -> (4.3387, 568.4365)
  line L21 (-12.41, 940.9591) -> (0.9859, 940.9591)
  line L22 (17.6623, 914.0986) -> (17.6623, 898.0623)
  line L23 (-12.41, 940.7228) -> (-12.41, 940.9591)
  line L24 (0.9859, 940.9591) -> (17.6623, 914.0986)
  line L25 (-5.0929, 912.6203) -> (2.8357, 899.3958)
  curve K3 (-7.4132, 913.7804) -> (-5.0929, 912.6203)
  line L26 (-12.41, 913.7938) -> (-7.4132, 913.7804)
  line L27 (4.3387, 899.8301) -> (4.3387, 913.7976)
  line L28 (4.3387, 913.7976) -> (-12.41, 940.7228)
  line L29 (16.6298, 896.9879) -> (-12.41, 896.9879)
  line L30 (-12.41, 896.9879) -> (-12.41, 913.7938)
  arc A1 centre (3.2063, 194.4628) radius 1.1324 between (3.2037, 193.3304) and (4.3387, 194.4628)
  arc A2 centre (3.1255, 194.3115) radius 0.9843 between (2.2512, 193.8596) and (3.2037, 193.3304)
  arc A3 centre (21.4136, 191.9466) radius 1.4314 between (21.4097, 190.5152) and (22.8437, 192.0075)
  arc A4 centre (3.4328, 552.9171) radius 0.9059 between (3.4307, 552.0112) and (4.3387, 552.9171)
  arc A5 centre (3.3682, 552.7961) radius 0.7874 between (2.6687, 552.4345) and (3.4307, 552.0112)
  arc A6 centre (17.9986, 550.9042) radius 1.1451 between (17.9955, 549.7591) and (19.1427, 550.9529)
  arc A7 centre (16.6326, 898.0185) radius 1.0306 between (16.6298, 896.9879) and (17.6623, 898.0623)
  arc A8 centre (3.4652, 899.7212) radius 0.7087 between (2.8357, 899.3958) and (3.5215, 899.0148)
  arc A9 centre (3.5234, 899.8301) radius 0.8153 between (3.5215, 899.0148) and (4.3387, 899.8301)
emboss "Emboss2" sketch "Sketch8" Depth -2 Horizontal Distance 0 Vertical Distance 0 Rotation Angle 0
emboss "Emboss2" sketch "Sketch8" Depth -2 Horizontal Distance 0 Vertical Distance 0 Rotation Angle 0
emboss "Emboss2" sketch "Sketch8" Depth -2 Horizontal Distance 0 Vertical Distance 0 Rotation Angle 0
work_plane "WorkPlane1" AlongDistance 70
sketch "Sketch1" plane through (0, 0, 1105.708) normal (0, 0, 1) x axis (1, 0, 0)
  line L1 (0, -8.7724) -> (0, 0)
  circle C1 centre (17.78, 0) radius 5.08
  point P1 (0, 0)
  point P2 (0, 0)
  point P4 (17.78, 0)
  coincident P1 P2
  vertical L1
  horizontal P1 P4
  dimension "d264" diameter C1 = 10.16
  dimension "d265" distance P1 P4 = 17.78
extrude "Extrude1" new body sketch "Sketch1" profile of C1 along normal blind 170 (= "50 mm + 120 mm")
sketch "Sketch2" plane through (0, 0, 1105.708) normal (0, 0, 1) x axis (1, 0, 0)
chamfer "Chamfer1" distance 3 Rotate Angle 75
fillet "Fillet1" radius 1.5 25
work_plane "WorkPlane2" AlongDistance 5.5
sketch "Sketch3" plane through (0, 5.5, 0) normal (0, 1, 0) x axis (1, 0, 0)
  line L1 (22.5, -1105.5) -> (12.5, -1105.5)
  line L2 (17.5, -1130.5) -> (17.5, -1105.5)
  line L3 (12.5, -1155.5) -> (22.5, -1155.5)
  point P4 (17.5, -1105.5)
  point P3 (22.5, -1105.5)
  point P6 (22.5, -1155.5)
  point P2 (12.5, -1105.5)
  point P7 (12.5, -1155.5)
  point P5 (17.5, -1130.5)
  midpoint L1 P4
  perpendicular L1 L2
  horizontal L3
  vertical P3 P6
  vertical P2 P7
  dimension "d274" distance P4 P5 = 25
  dimension "d280" distance L1 L3 = 50
split_face "SplitFace1"
as_built_joint "As-built7"
rectangular_pattern "00000000-0000-0000-0000-000000000000" uSpaceDistance -35 vSpaceDistance 0
sketch "Sketch1" plane through (0, 0, 1105.708) normal (0, 0, -1) x axis (1, 0, 0)
  circle C1 centre (17.78, 0) radius 5.08
  circle C2 centre (17.78, 0) radius 5.08
  circle C3 centre (-17.22, 0) radius 5.08
  circle C4 centre (-17.22, 0) radius 9.08
  circle C5 centre (17.78, 0) radius 9.08
  dimension "d285" = 4
  dimension "d286" = 4
extrude "Extrude1" new body sketch "Sketch1" against normal blind 50 bodies "Preserve1", "Preserve2"
sketch "Sketch2" plane through (0, 0, 1035.708) normal (0, 0, 1) x axis (-1, 0, 0)
  circle C1 centre (0, 0) radius 2.117
  circle C2 centre (-14.1421, 14.1421) radius 2.117
  circle C3 centre (0, 12) radius 2.117
  circle C4 centre (-20, 0) radius 2.117
  circle C5 centre (-8.4853, 8.4853) radius 2.117
  circle C6 centre (-14.1421, -14.1421) radius 2.117
  circle C7 centre (-12, 0) radius 2.117
  circle C8 centre (0, -20) radius 2.117
  circle C9 centre (-8.4853, -8.4853) radius 2.117
  circle C10 centre (14.1421, -14.1421) radius 2.117
  circle C11 centre (0, -12) radius 2.117
  circle C12 centre (20, 0) radius 2.117
  circle C13 centre (8.4853, -8.4853) radius 2.117
  circle C14 centre (14.1421, 14.1421) radius 2.117
  circle C15 centre (12, 0) radius 2.117
  circle C16 centre (0, 20) radius 2.117
  circle C17 centre (8.4853, 8.4853) radius 2.117
  circle C18 centre (0, 0) radius 27.305
  circle C19 centre (-14.1421, 14.1421) radius 2.117
  circle C20 centre (-14.1421, -14.1421) radius 2.117
  circle C21 centre (14.1421, -14.1421) radius 2.117
  circle C22 centre (14.1421, 14.1421) radius 2.117
  circle C23 centre (14.1421, -14.1421) radius 5.117
  circle C24 centre (-14.1421, -14.1421) radius 5.117
  circle C25 centre (-14.1421, 14.1421) radius 5.117
  circle C26 centre (14.1421, 14.1421) radius 5.117
  dimension "d289" = 3
  dimension "d290" = 3
  dimension "d291" = 3
  dimension "d292" = 3
extrude "Extrude2" new body sketch "Sketch2" profile of C2 C6 C10 C14 C19 C20 C21 C22 C23 C24 C25 C26 along normal blind 5 bodies "Preserve3", "Preserve4", "Preserve5", "Preserve6"
as_built_joint "As-built1"
extrude "Extrude3" new body sketch "Sketch2" profile of C2 C6 C10 C14 C19 C20 C21 C22 to an object bodies "Obstacle1", "Obstacle2", "Obstacle3", "Obstacle4"
sketch "Sketch4" plane through (0, 0, 1040.708) normal (0, 0, 1) x axis (-1, 0, 0)
  circle C1 centre (14.1421, -14.1421) radius 2.117
  circle C2 centre (14.1421, -14.1421) radius 5.117
  circle C3 centre (14.1421, -14.1421) radius 5.117
  circle C4 centre (-14.1421, -14.1421) radius 5.117
  circle C5 centre (-14.1421, 14.1421) radius 5.117
  circle C6 centre (14.1421, 14.1421) radius 5.117
extrude "Extrude4" add sketch "Sketch4" along normal blind 50
sketch "Sketch5" plane through (0, 0, 1105.708) normal (0, 0, -1) x axis (1, 0, 0)
  circle C1 centre (17.78, 0) radius 5.08
  circle C2 centre (17.78, 0) radius 9.08
  circle C3 centre (17.78, 0) radius 9.08
  circle C4 centre (-17.22, 0) radius 9.08
extrude "Extrude5" add sketch "Sketch5" along normal blind 5
sketch "Sketch1" plane through (0, 0, 1105.708) normal (0, 0, -1) x axis (1, 0, 0)
  circle C1 centre (17.78, 0) radius 5.08
  circle C2 centre (17.78, 0) radius 5.08
  circle C3 centre (-17.22, 0) radius 5.08
  circle C4 centre (-17.22, 0) radius 9.08
  circle C5 centre (17.78, 0) radius 9.08
  dimension "d285_1" = 4
  dimension "d286_1" = 4
extrude "Extrude1" new body sketch "Sketch1" against normal blind 50 named "d287_1"
sketch "Sketch2" plane through (0, 0, 1035.708) normal (0, 0, 1) x axis (-1, 0, 0)
  circle C1 centre (0, 0) radius 2.117
  circle C2 centre (-14.1421, 14.1421) radius 2.117
  circle C3 centre (0, 12) radius 2.117
  circle C4 centre (-20, 0) radius 2.117
  circle C5 centre (-8.4853, 8.4853) radius 2.117
  circle C6 centre (-14.1421, -14.1421) radius 2.117
  circle C7 centre (-12, 0) radius 2.117
  circle C8 centre (0, -20) radius 2.117
  circle C9 centre (-8.4853, -8.4853) radius 2.117
  circle C10 centre (14.1421, -14.1421) radius 2.117
  circle C11 centre (0, -12) radius 2.117
  circle C12 centre (20, 0) radius 2.117
  circle C13 centre (8.4853, -8.4853) radius 2.117
  circle C14 centre (14.1421, 14.1421) radius 2.117
  circle C15 centre (12, 0) radius 2.117
  circle C16 centre (0, 20) radius 2.117
  circle C17 centre (8.4853, 8.4853) radius 2.117
  circle C18 centre (0, 0) radius 27.305
  circle C19 centre (-14.1421, 14.1421) radius 2.117
  circle C20 centre (-14.1421, -14.1421) radius 2.117
  circle C21 centre (14.1421, -14.1421) radius 2.117
  circle C22 centre (14.1421, 14.1421) radius 2.117
  circle C23 centre (14.1421, -14.1421) radius 5.117
  circle C24 centre (-14.1421, -14.1421) radius 5.117
  circle C25 centre (-14.1421, 14.1421) radius 5.117
  circle C26 centre (14.1421, 14.1421) radius 5.117
  dimension "d289_1" = 3
  dimension "d290_1" = 3
  dimension "d291_1" = 3
  dimension "d292_1" = 3
extrude "Extrude2" new body sketch "Sketch2" profile of C2 C6 C10 C14 C19 C20 C21 C22 C23 C24 C25 C26 along normal blind 5 named "d293_1" bodies "Connection1", "Connection2", "Connection3", "Connection4"
extrude "Extrude3" new body sketch "Sketch2" profile of C2 C6 C10 C14 C19 C20 C21 C22 to an object bodies "Avoid1", "Avoid2", "Avoid3", "Avoid4"
sketch "Sketch4" plane through (0, 0, 1040.708) normal (0, 0, 1) x axis (-1, 0, 0)
  circle C1 centre (14.1421, -14.1421) radius 2.117
  circle C2 centre (14.1421, -14.1421) radius 5.117
  circle C3 centre (14.1421, -14.1421) radius 5.117
  circle C4 centre (-14.1421, -14.1421) radius 5.117
  circle C5 centre (-14.1421, 14.1421) radius 5.117
  circle C6 centre (14.1421, 14.1421) radius 5.117
extrude "Extrude4" add sketch "Sketch4" along normal blind 50 named "d297_1"
sketch "Sketch5" plane through (0, 0, 1105.708) normal (0, 0, -1) x axis (1, 0, 0)
  circle C1 centre (17.78, 0) radius 5.08
  circle C2 centre (17.78, 0) radius 9.08
  circle C3 centre (17.78, 0) radius 9.08
  circle C4 centre (-17.22, 0) radius 9.08
extrude "Extrude5" add sketch "Sketch5" along normal blind 5 named "d299_1"
position "Position1" RotateAboutZ -98.9 RotateAboutZ 90 RotateAboutZ -23.6 RotateAboutZ 15
as_built_joint "As-built2"
remove_body "RemoveBody10"
remove_body "RemoveBody11"
base_feature "Base Feature"
sketch "Sketch1" plane through (0, 0, 1105.5) normal (0, 0, -1) x axis (1, 0, 0)
  circle C1 centre (17.5, 0) radius 5
  circle C2 centre (17.5, 0) radius 5
  circle C3 centre (-17.5, 0) radius 5
  circle C4 centre (-17.5, 0) radius 9
  circle C5 centre (17.5, 0) radius 9
  dimension "d285_2" = 4
  dimension "d286_2" = 4
  dimension "d343" OffsetThickness = 2
  dimension "d344" OffsetBlendDistance = 0.872
sketch "Sketch2" plane through (0, 0, 1035.5) normal (0, 0, 1) x axis (-1, 0, 0)
  circle C1 centre (0, 0) radius 2.117
  circle C2 centre (-14.1421, 14.1421) radius 2.117
  circle C3 centre (0, 12) radius 2.117
  circle C4 centre (-20, 0) radius 2.117
  circle C5 centre (-8.4853, 8.4853) radius 2.117
  circle C6 centre (-14.1421, -14.1421) radius 2.117
  circle C7 centre (-12, 0) radius 2.117
  circle C8 centre (0, -20) radius 2.117
  circle C9 centre (-8.4853, -8.4853) radius 2.117
  circle C10 centre (14.1421, -14.1421) radius 2.117
  circle C11 centre (0, -12) radius 2.117
  circle C12 centre (20, 0) radius 2.117
  circle C13 centre (8.4853, -8.4853) radius 2.117
  circle C14 centre (14.1421, 14.1421) radius 2.117
  circle C15 centre (12, 0) radius 2.117
  circle C16 centre (0, 20) radius 2.117
  circle C17 centre (8.4853, 8.4853) radius 2.117
  circle C18 centre (0, 0) radius 27.5
  circle C19 centre (-14.1421, 14.1421) radius 2.117
  circle C20 centre (-14.1421, -14.1421) radius 2.117
  circle C21 centre (14.1421, -14.1421) radius 2.117
  circle C22 centre (14.1421, 14.1421) radius 2.117
  circle C23 centre (14.1421, -14.1421) radius 5.117
  circle C24 centre (-14.1421, -14.1421) radius 5.117
  circle C25 centre (-14.1421, 14.1421) radius 5.117
  circle C26 centre (14.1421, 14.1421) radius 5.117
  dimension "d289_2" = 3
  dimension "d290_2" = 3
  dimension "d291_2" = 3
  dimension "d292_2" = 3
form "Feature1" bodies "Body15"
base_feature "Feature" bodies "Preserve1 (1)", "Preserve2 (1)", "Preserve3 (1)", "Preserve4 (1)", "Preserve5 (1)", "Preserve6 (1)"
form "Feature2" bodies "Body17", "Body18", "Body18 (1)"
boundary_fill "BoundaryFill1"
joint "Assemble9" alignAngle 180 alignOffsetX 0 alignOffsetY 0 alignOffsetZ 0
remove_body "RemoveBody10"
step "Screw17"
joint "Assemble18" alignAngle 0 alignOffsetX 0 alignOffsetY 0 alignOffsetZ 0
step "Screw18"
joint "Assemble19" alignAngle 0 alignOffsetX 0 alignOffsetY 0 alignOffsetZ 0
step "Screw19"
joint "Assemble20" alignOffsetX 0 alignOffsetY 0 alignOffsetZ 0
step "Screw20"
joint "Assemble21" alignAngle 0 alignOffsetX 0 alignOffsetY 0 alignOffsetZ 0
step "Screw21"
joint "Assemble22" alignAngle 0 alignOffsetX 0 alignOffsetY 0 alignOffsetZ 0
step "Screw22"
joint "Assemble23" alignAngle 0 alignOffsetX 0 alignOffsetY 0 alignOffsetZ 0
step "Screw23"
joint "Assemble24" alignAngle 0 alignOffsetX 0 alignOffsetY 0 alignOffsetZ 0
step "Screw24"
joint "Assemble25" alignAngle 0 alignOffsetX 0 alignOffsetY 0 alignOffsetZ 0
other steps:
fillet "Fillet1" radius 10
thread "Thread1" ThreadOffset 0 ThreadDepth 7.4
thread "Thread2" ThreadOffset 0 ThreadDepth 7.4
thread "Thread3" ThreadOffset 0 ThreadDepth 7.4
hole "Hole2" HoleDepth 20 HoleDiameter 4.234 TipAngle 180
thread "Thread1" ThreadOffset 0 ThreadDepth 7.4
hole "Hole3" HoleDepth 20 HoleDiameter 4.234 TipAngle 180
thread "Thread2" ThreadOffset 0 ThreadDepth 7.4
revolve "Revolve2" sketch "Sketch5" AlongAngle 360
create_component "CreateComponent1"
create_component "CreateComponent2"
create_component "CreateComponent3"
create_component "CreateComponent4"
create_component "CreateComponent5"
create_component "CreateComponent6"
create_component "CreateComponent7"
create_component "CreateComponent8"
create_component "CreateComponent1"
create_component "CreateComponent2"
create_component "CreateComponent3"
remove_body "RemoveBody1"
remove_body "RemoveBody2"
remove_body "RemoveBody3"
remove_body "RemoveBody4"
remove_body "RemoveBody5"
remove_body "RemoveBody6"
remove_body "RemoveBody7"
remove_body "RemoveBody8"
remove_body "RemoveBody9"
create_component "CreateComponent4"
joint_origin "JointOrigin1"
joint_origin "JointOrigin9"
joint_origin "JointOrigin18"
joint_origin "JointOrigin19"
joint_origin "JointOrigin20"
joint_origin "JointOrigin21"
joint_origin "JointOrigin22"
joint_origin "JointOrigin23"
joint_origin "JointOrigin24"
joint_origin "JointOrigin25"
named bodies: "Preserve1", "Preserve2", "Preserve3", "Preserve4", "Preserve5", "Preserve6", "Obstacle1", "Obstacle2", "Obstacle3", "Obstacle4", "Connection1", "Connection2", "Connection3", "Connection4", "Avoid1", "Avoid2", "Avoid3", "Avoid4", "Body15", "Preserve1 (1)", "Preserve2 (1)", "Preserve3 (1)", "Preserve4 (1)", "Preserve5 (1)", "Preserve6 (1)", "Body17", "Body18", "Body18 (1)"

design "Hexagon Socket Head Cap Screw ANSI B18.3 - 1/4-28 UNF x 3/8 Steel Grade 2 Plain"
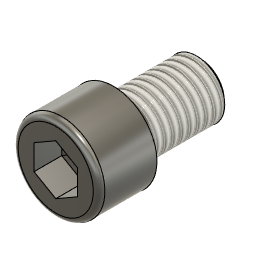
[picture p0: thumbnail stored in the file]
description: Hexagon Socket Head Cap Screw ANSI B18.3 - 1/4-28 UNF x 3/8
part number: arrangementsContainer
parameter "adsk_nomlen" = 9.525
parameter "adsk_headh" = 6.35
parameter "adsk_headdia" = 9.525
parameter "adsk_nomdia" = 6.35
parameter "adsk_philwidth" = 4.7752
parameter "adsk_phildepth" = 3.048
parameter "adsk_thrlen" = 8.1641
parameter "adsk_startlen" = 0.541
parameter "adsk_endpointdia" = 5.268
